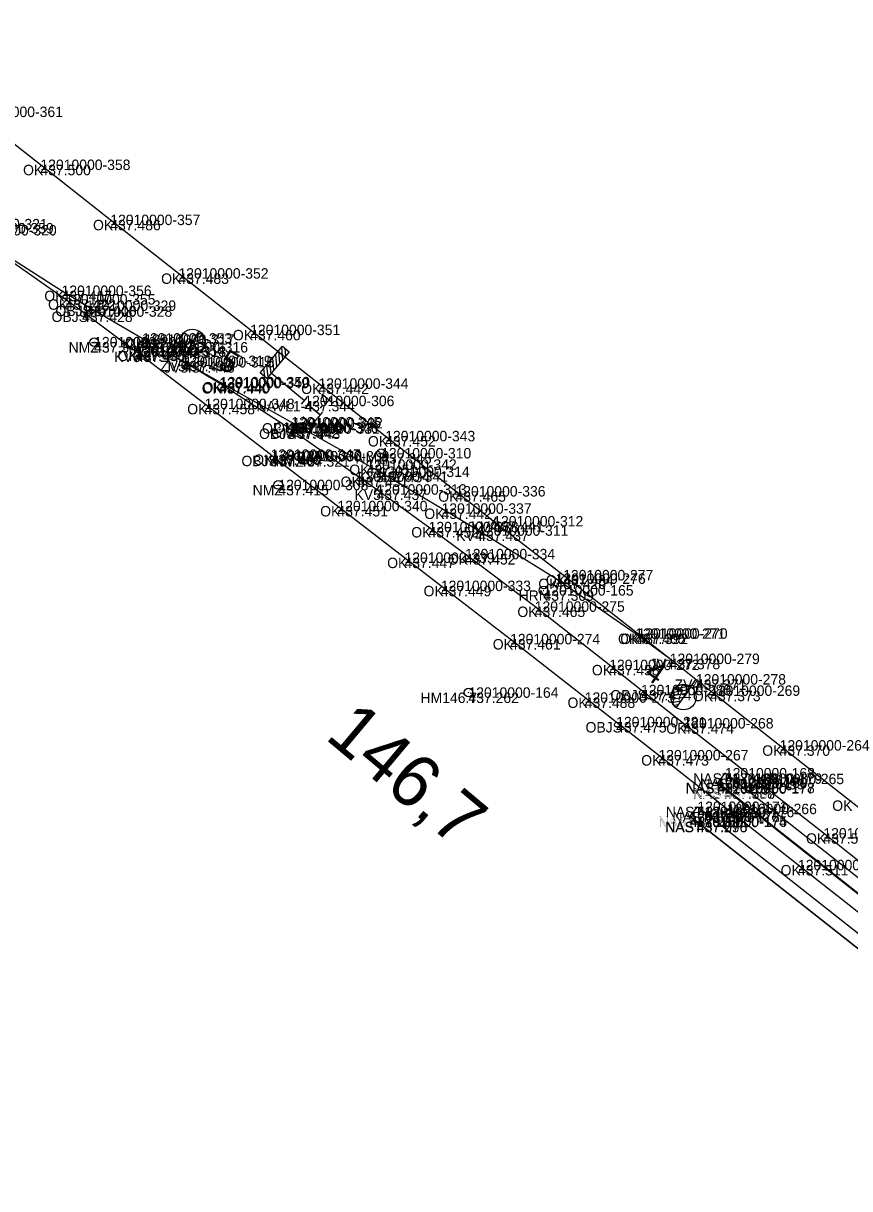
# Model space of a CAD drawing. Extents: x -653665 to -652742, y -1166300 to -1165487.
# Drawn here: x -653400 to -653305, y -1165811.3 to -1165677.3 of the extents above; entities that cross this region are included whole.
import ezdxf

# ---------------------------------------------------------------- set-up
doc = ezdxf.new("R2010")
doc.units = 0
for name, color, linetype in [('Vrstva 1', 7, 'Continuous'), ('Vrstva 14', 7, 'Continuous'), ('Vrstva 2', 7, 'Continuous'), ('Vrstva 50', 7, 'Continuous'), ('Vrstva 6', 7, 'Continuous'), ('Vrstva 60', 7, 'Continuous'), ('Vrstva 61', 7, 'Continuous'), ('Vrstva 62', 7, 'Continuous'), ('Vrstva 7', 7, 'Continuous')]:
    doc.layers.add(name, color=color, linetype=linetype)

msp = doc.modelspace()

# ---------------------------------------------------------------- linework, layer by layer
at = {"layer": 'Vrstva 1'}
for points in [[(-653322.72, -1165752.72), (-653325.73, -1165750.35), (-653329.43, -1165747.45), (-653337.98, -1165740.73), (-653346.02, -1165734.53), (-653350.36, -1165731.09), (-653358.44, -1165724.74), (-653366.11, -1165718.7), (-653373.96, -1165712.53), (-653382.2, -1165706.04), (-653390.04, -1165699.88), (-653398.07, -1165693.55), (-653405.83, -1165687.47), (-653413.9, -1165681.16), (-653418.86, -1165677.28)], [(-653303.11, -1165780.26), (-653310.99, -1165774.05), (-653319.17, -1165767.61), (-653327.03, -1165761.43), (-653331.89, -1165757.62), (-653335.5, -1165754.8), (-653344.08, -1165748.08), (-653352.04, -1165741.96), (-653356.22, -1165738.72), (-653363.93, -1165732.78), (-653371.45, -1165727), (-653371.62, -1165726.86), (-653379.2, -1165721.04), (-653387.07, -1165715.03), (-653387.21, -1165714.92), (-653393.27, -1165710.42), (-653395.2, -1165709.02), (-653406.55, -1165701.06), (-653406.89, -1165700.83), (-653407.58, -1165700.37)], [(-653381.84, -1165716.08), (-653384.56, -1165714.53), (-653386.13, -1165713.64), (-653386.38, -1165713.51), (-653392.82, -1165709.75), (-653395.64, -1165708.03), (-653406.55, -1165701.06), (-653406.89, -1165700.83), (-653407.58, -1165700.37)], [(-653322.72, -1165752.72), (-653325.73, -1165750.35), (-653329.7, -1165747.45), (-653338.85, -1165741.13), (-653347.74, -1165735.6), (-653351.96, -1165733.07), (-653359.08, -1165728.84), (-653360.57, -1165728.02), (-653369.24, -1165723.15), (-653377.44, -1165718.54), (-653381.54, -1165716.25), (-653381.84, -1165716.08)], [(-653300.38, -1165776.48), (-653308.07, -1165770.41), (-653316.04, -1165764.16), (-653324.15, -1165757.77), (-653329.03, -1165753.94), (-653332.69, -1165751.05), (-653341.25, -1165744.34), (-653349.26, -1165738.31), (-653353.45, -1165735.2), (-653359.43, -1165730.88), (-653361.58, -1165729.39), (-653369.56, -1165723.78), (-653377.53, -1165718.65), (-653381.54, -1165716.25), (-653381.84, -1165716.08)], [(-653297.59, -1165772.52), (-653305.06, -1165766.63), (-653313.1, -1165760.3), (-653321.09, -1165754.02), (-653322.72, -1165752.72)]]:
    msp.add_lwpolyline(points, dxfattribs=at)
at = {"layer": 'Vrstva 14'}
for points in [[(-653264.73, -1165806.58), (-653318.56, -1165764.12), (-653319.39, -1165763.51), (-653320.24, -1165764.59), (-653320.26, -1165764.64), (-653319.44, -1165765.26), (-653265.62, -1165807.73), (-653264.04, -1165808.96), (-653264.01, -1165808.93), (-653258.45, -1165813.32), (-653255.28, -1165815.81), (-653252.89, -1165817.67), (-653252.91, -1165817.71), (-653185.94, -1165870.54), (-653160.89, -1165890.22), (-653160.13, -1165890.87), (-653160.09, -1165890.83), (-653159.23, -1165889.74), (-653160.03, -1165889.1), (-653185.12, -1165869.34), (-653252.03, -1165816.59), (-653254.4, -1165814.7), (-653257.6, -1165812.25), (-653263.18, -1165807.82)], [(-653323.43, -1165768.49), (-653323.42, -1165768.47), (-653322.55, -1165767.36), (-653321.77, -1165767.96), (-653260.92, -1165815.93), (-653260.66, -1165816.11), (-653257.48, -1165818.59), (-653188.19, -1165873.27), (-653163.42, -1165892.82), (-653162.59, -1165893.47), (-653163.54, -1165894.55), (-653163.55, -1165894.57), (-653164.32, -1165893.92), (-653188.97, -1165874.49), (-653261.81, -1165817.03), (-653322.62, -1165769.1)]]:
    msp.add_lwpolyline(points, close=True, dxfattribs=at)
for points in [[(-653320.24, -1165764.59), (-653319.41, -1165765.19), (-653265.58, -1165807.68), (-653264.01, -1165808.93)], [(-653323.42, -1165768.47), (-653322.59, -1165769.06), (-653261.78, -1165817.01), (-653188.99, -1165874.41), (-653164.29, -1165893.89), (-653163.54, -1165894.55)]]:
    msp.add_lwpolyline(points, dxfattribs=at)
at = {"layer": 'Vrstva 2'}
for p, q in [((-653385.88, -1165713.21), (-653386.38, -1165714.08)), ((-653381.33, -1165715.19), (-653379.87, -1165712.66)), ((-653380.59, -1165713.91), (-653379.19, -1165713.53)), ((-653380.32, -1165713.45), (-653379.34, -1165713.18)), ((-653380.06, -1165712.99), (-653379.6, -1165712.86)), ((-653386.78, -1165714.62), (-653387.36, -1165715.44)), ((-653381.23, -1165715.24), (-653379.4, -1165714.75)), ((-653381.12, -1165714.82), (-653379.19, -1165714.31)), ((-653380.86, -1165714.37), (-653379.14, -1165713.91)), ((-653381.33, -1165715.19), (-653381.84, -1165716.08)), ((-653381.33, -1165715.19), (-653381.33, -1165715.19)), ((-653358.83, -1165728.4), (-653359.33, -1165729.27)), ((-653359.14, -1165730.47), (-653359.72, -1165731.29)), ((-653347.49, -1165735.16), (-653347.99, -1165736.03)), ((-653345.73, -1165734.12), (-653346.3, -1165734.94)), ((-653323.55, -1165753.91), (-653325.52, -1165754.25)), ((-653323.4, -1165753.5), (-653325.27, -1165753.83)), ((-653323.31, -1165753.56), (-653324.99, -1165755.96)), ((-653323.31, -1165753.56), (-653322.72, -1165752.72)), ((-653323.31, -1165753.56), (-653323.31, -1165753.56)), ((-653323.85, -1165754.34), (-653325.6, -1165754.65)), ((-653324.16, -1165754.78), (-653325.58, -1165755.03)), ((-653324.46, -1165755.21), (-653325.46, -1165755.39)), ((-653324.77, -1165755.65), (-653325.24, -1165755.73))]:
    msp.add_line(p, q, dxfattribs=at)
for centre in [(-653380.6, -1165713.92), (-653324.15, -1165754.76)]:
    msp.add_circle(centre, 1.46, dxfattribs=at)
for centre, start, end in [((-653380.6, -1165713.93), 240.0196, 59.9804), ((-653324.15, -1165754.76), 55.0196, 234.9804)]:
    msp.add_arc(centre, 1.46, start, end, dxfattribs=at)
at = {"layer": 'Vrstva 50'}
for p, q in [((-653391.94, -1165713.94), (-653391.84, -1165713.94)), ((-653368.36, -1165727.06), (-653368.26, -1165727.06)), ((-653358.95, -1165726.71), (-653358.85, -1165726.71)), ((-653370.77, -1165730.36), (-653370.67, -1165730.36)), ((-653340.29, -1165742.48), (-653340.19, -1165742.48))]:
    msp.add_line(p, q, dxfattribs=at)
for centre in [(-653391.89, -1165713.94), (-653368.31, -1165727.06), (-653358.9, -1165726.71), (-653370.72, -1165730.36), (-653340.24, -1165742.48)]:
    msp.add_circle(centre, 0.5, dxfattribs=at)
at = {"layer": 'Vrstva 6'}
for p, q in [((-653370.7, -1165714.95), (-653370.58, -1165716.35)), ((-653370.36, -1165714.54), (-653370.24, -1165715.95)), ((-653369.97, -1165714.64), (-653369.9, -1165715.54)), ((-653371.72, -1165716.16), (-653371.6, -1165717.57)), ((-653371.38, -1165715.76), (-653371.26, -1165717.17)), ((-653371.04, -1165715.35), (-653370.92, -1165716.76)), ((-653372.41, -1165716.98), (-653372.32, -1165717.89)), ((-653372.07, -1165716.57), (-653371.94, -1165717.98)), ((-653367.73, -1165720.7), (-653371.54, -1165717.5)), ((-653368.05, -1165721.08), (-653367.4, -1165720.32))]:
    msp.add_line(p, q, dxfattribs=at)
msp.add_lwpolyline([(-653372.06, -1165718.11), (-653372.82, -1165717.47), (-653370.25, -1165714.41), (-653369.48, -1165715.05)], close=True, dxfattribs=at)
at = {"layer": 'Vrstva 60'}
for p, q in [((-653398.07, -1165693.55), (-653398.07, -1165693.55)), ((-653390.04, -1165699.88), (-653390.04, -1165699.88)), ((-653382.2, -1165706.04), (-653382.2, -1165706.04)), ((-653395.64, -1165708.03), (-653395.64, -1165708.03)), ((-653395.2, -1165709.02), (-653395.2, -1165709.02)), ((-653392.82, -1165709.75), (-653392.82, -1165709.75)), ((-653393.27, -1165710.42), (-653393.27, -1165710.42)), ((-653386.38, -1165713.51), (-653386.38, -1165713.51)), ((-653386.13, -1165713.64), (-653386.13, -1165713.64)), ((-653373.96, -1165712.53), (-653373.96, -1165712.53)), ((-653391.89, -1165713.94), (-653391.89, -1165713.94)), ((-653387.21, -1165714.92), (-653387.21, -1165714.92)), ((-653387.07, -1165715.03), (-653387.07, -1165715.03)), ((-653384.56, -1165714.53), (-653384.56, -1165714.53)), ((-653381.84, -1165716.08), (-653381.84, -1165716.08)), ((-653381.54, -1165716.25), (-653381.54, -1165716.25)), ((-653377.53, -1165718.65), (-653377.53, -1165718.65)), ((-653377.44, -1165718.54), (-653377.44, -1165718.54)), ((-653366.11, -1165718.7), (-653366.11, -1165718.7)), ((-653379.2, -1165721.04), (-653379.2, -1165721.04)), ((-653367.73, -1165720.7), (-653367.73, -1165720.7)), ((-653369.24, -1165723.15), (-653369.24, -1165723.15)), ((-653369.56, -1165723.78), (-653369.56, -1165723.78)), ((-653369.41, -1165723.87), (-653369.41, -1165723.87)), ((-653369.07, -1165723.25), (-653369.07, -1165723.25)), ((-653358.44, -1165724.74), (-653358.44, -1165724.74)), ((-653371.62, -1165726.86), (-653371.62, -1165726.86)), ((-653371.45, -1165727), (-653371.45, -1165727)), ((-653368.31, -1165727.06), (-653368.31, -1165727.06)), ((-653358.9, -1165726.71), (-653358.9, -1165726.71)), ((-653360.57, -1165728.02), (-653360.57, -1165728.02)), ((-653361.58, -1165729.39), (-653361.58, -1165729.39)), ((-653359.08, -1165728.84), (-653359.08, -1165728.84)), ((-653370.72, -1165730.36), (-653370.72, -1165730.36)), ((-653359.43, -1165730.88), (-653359.43, -1165730.88)), ((-653350.36, -1165731.09), (-653350.36, -1165731.09)), ((-653363.93, -1165732.78), (-653363.93, -1165732.78)), ((-653351.96, -1165733.07), (-653351.96, -1165733.07)), ((-653353.45, -1165735.2), (-653353.45, -1165735.2)), ((-653346.02, -1165734.53), (-653346.02, -1165734.53)), ((-653347.74, -1165735.6), (-653347.74, -1165735.6)), ((-653356.22, -1165738.72), (-653356.22, -1165738.72)), ((-653349.26, -1165738.31), (-653349.26, -1165738.31)), ((-653338.85, -1165741.13), (-653338.85, -1165741.13)), ((-653337.98, -1165740.73), (-653337.98, -1165740.73)), ((-653352.04, -1165741.96), (-653352.04, -1165741.96)), ((-653340.24, -1165742.48), (-653340.24, -1165742.48)), ((-653341.25, -1165744.34), (-653341.25, -1165744.34)), ((-653344.08, -1165748.08), (-653344.08, -1165748.08)), ((-653329.7, -1165747.45), (-653329.7, -1165747.45)), ((-653329.43, -1165747.45), (-653329.43, -1165747.45)), ((-653332.69, -1165751.05), (-653332.69, -1165751.05)), ((-653325.73, -1165750.35), (-653325.73, -1165750.35)), ((-653329.03, -1165753.94), (-653329.03, -1165753.94)), ((-653322.72, -1165752.72), (-653322.72, -1165752.72)), ((-653348.87, -1165754.23), (-653348.87, -1165754.23)), ((-653335.5, -1165754.8), (-653335.5, -1165754.8)), ((-653321.09, -1165754.02), (-653321.09, -1165754.02)), ((-653331.89, -1165757.62), (-653331.89, -1165757.62)), ((-653324.15, -1165757.77), (-653324.15, -1165757.77)), ((-653313.1, -1165760.3), (-653313.1, -1165760.3)), ((-653327.03, -1165761.43), (-653327.03, -1165761.43)), ((-653320.26, -1165764.64), (-653320.26, -1165764.64)), ((-653320.24, -1165764.59), (-653320.24, -1165764.59)), ((-653319.39, -1165763.51), (-653319.39, -1165763.51)), ((-653318.56, -1165764.12), (-653318.56, -1165764.12)), ((-653316.04, -1165764.16), (-653316.04, -1165764.16)), ((-653319.44, -1165765.26), (-653319.44, -1165765.26)), ((-653319.41, -1165765.19), (-653319.41, -1165765.19)), ((-653322.55, -1165767.36), (-653322.55, -1165767.36)), ((-653305.06, -1165766.63), (-653305.06, -1165766.63)), ((-653323.43, -1165768.49), (-653323.43, -1165768.49)), ((-653323.42, -1165768.47), (-653323.42, -1165768.47)), ((-653321.77, -1165767.96), (-653321.77, -1165767.96)), ((-653319.17, -1165767.61), (-653319.17, -1165767.61)), ((-653322.62, -1165769.1), (-653322.62, -1165769.1)), ((-653322.59, -1165769.06), (-653322.59, -1165769.06)), ((-653308.07, -1165770.41), (-653308.07, -1165770.41)), ((-653310.99, -1165774.05), (-653310.99, -1165774.05))]:
    msp.add_line(p, q, dxfattribs=at)
at = {"layer": 'Vrstva 7'}
msp.add_line((-653348.91, -1165754.2), (-653348.83, -1165754.27), dxfattribs=at)
msp.add_circle((-653348.87, -1165754.23), 0.5, dxfattribs=at)

# ---------------------------------------------------------------- texts
at = {"layer": 'Vrstva 2'}
for s, rotation, p in [('5', 330, (-653377.78, -1165716.8)), ('4', 325, (-653328.83, -1165752.37))]:
    msp.add_text(s, height=2.5, rotation=rotation, dxfattribs=at).set_placement(p)
at = {"layer": 'Vrstva 6'}
msp.add_text('L1-4', height=1.5, rotation=50, dxfattribs=at).set_placement((-653366.94, -1165723.67))
at = {"layer": 'Vrstva 60'}
for s, p in [('12010000-361', (-653405.83, -1165688.06)), ('12010000-358', (-653398.07, -1165694.15)), ('12010000-321', (-653407.58, -1165700.97)), ('12010000-359', (-653406.89, -1165701.44)), ('12010000-357', (-653390.04, -1165700.48)), ('12010000-320', (-653406.55, -1165701.67)), ('12010000-352', (-653382.2, -1165706.64)), ('12010000-356', (-653395.64, -1165708.63)), ('12010000-355', (-653395.2, -1165709.62)), ('12010000-329', (-653392.82, -1165710.35)), ('12010000-328', (-653393.27, -1165711.02)), ('12010000-351', (-653373.96, -1165713.13)), ('12010000-303', (-653391.89, -1165714.54)), ('12010000-353', (-653386.38, -1165714.11)), ('12010000-317', (-653386.13, -1165714.24)), ('12010000-354', (-653387.21, -1165715.52)), ('12010000-318', (-653387.07, -1165715.63)), ('12010000-316', (-653384.56, -1165715.13)), ('12010000-319', (-653381.84, -1165716.69)), ('12010000-315', (-653381.54, -1165716.85)), ('12010000-349', (-653377.53, -1165719.25)), ('12010000-350', (-653377.44, -1165719.14)), ('12010000-344', (-653366.11, -1165719.3)), ('12010000-348', (-653379.2, -1165721.64)), ('12010000-306', (-653367.73, -1165721.3)), ('12010000-346', (-653369.56, -1165724.38)), ('12010000-345', (-653369.24, -1165723.75)), ('12010000-332', (-653369.07, -1165723.85)), ('12010000-331', (-653369.41, -1165724.47)), ('12010000-343', (-653358.44, -1165725.34)), ('12010000-347', (-653371.62, -1165727.47)), ('12010000-330', (-653371.45, -1165727.6)), ('12010000-309', (-653368.31, -1165727.66)), ('12010000-310', (-653358.9, -1165727.31)), ('12010000-342', (-653360.57, -1165728.62)), ('12010000-314', (-653359.08, -1165729.44)), ('12010000-308', (-653370.72, -1165730.96)), ('12010000-341', (-653361.58, -1165729.99)), ('12010000-313', (-653359.43, -1165731.48)), ('12010000-336', (-653350.36, -1165731.69)), ('12010000-340', (-653363.93, -1165733.38)), ('12010000-337', (-653351.96, -1165733.67)), ('12010000-338', (-653353.45, -1165735.8)), ('12010000-311', (-653347.74, -1165736.2)), ('12010000-312', (-653346.02, -1165735.13)), ('12010000-334', (-653349.26, -1165738.91)), ('12010000-339', (-653356.22, -1165739.32)), ('12010000-276', (-653338.85, -1165741.73)), ('12010000-277', (-653337.98, -1165741.33)), ('12010000-333', (-653352.04, -1165742.56)), ('12010000-165', (-653340.24, -1165743.08)), ('12010000-275', (-653341.25, -1165744.94)), ('12010000-271', (-653329.7, -1165748.05)), ('12010000-270', (-653329.43, -1165748.04)), ('12010000-274', (-653344.08, -1165748.68)), ('12010000-279', (-653325.73, -1165750.95)), ('12010000-272', (-653332.69, -1165751.65)), ('12010000-278', (-653322.72, -1165753.31)), ('12010000-164', (-653348.87, -1165754.83)), ('12010000-280', (-653329.03, -1165754.54)), ('12010000-269', (-653321.09, -1165754.61)), ('12010000-273', (-653335.5, -1165755.4)), ('12010000-281', (-653331.89, -1165758.22)), ('12010000-268', (-653324.15, -1165758.36)), ('12010000-264', (-653313.1, -1165760.9)), ('12010000-267', (-653327.03, -1165762.03)), ('12010000-168', (-653319.39, -1165764.1)), ('12010000-170', (-653320.26, -1165765.24)), ('12010000-169', (-653320.24, -1165765.19)), ('12010000-177', (-653319.44, -1165765.86)), ('12010000-178', (-653319.41, -1165765.79)), ('12010000-179', (-653318.56, -1165764.72)), ('12010000-265', (-653316.04, -1165764.76)), ('12010000-171', (-653322.55, -1165767.96)), ('12010000-176', (-653321.77, -1165768.56)), ('12010000-266', (-653319.17, -1165768.21)), ('12010000-173', (-653323.43, -1165769.09)), ('12010000-172', (-653323.42, -1165769.07)), ('12010000-174', (-653322.62, -1165769.7)), ('12010000-175', (-653322.59, -1165769.66)), ('12010000-262', (-653308.07, -1165771.01)), ('12010000-261', (-653310.99, -1165774.66))]:
    msp.add_text(s, height=1.2, dxfattribs=at).set_placement(p)
at = {"layer": 'Vrstva 61'}
for s, p in [('437.500', (-653398.07, -1165694.75)), ('437.486', (-653390.04, -1165701.08)), ('437.483', (-653382.2, -1165707.24)), ('437.417', (-653395.64, -1165709.23)), ('437.422', (-653395.2, -1165710.22)), ('437.418', (-653392.82, -1165710.95)), ('437.428', (-653393.27, -1165711.62)), ('437.446', (-653386.38, -1165714.71)), ('437.441', (-653386.13, -1165714.84)), ('437.460', (-653373.96, -1165713.73)), ('437.343', (-653391.89, -1165715.14)), ('437.436', (-653387.21, -1165716.12)), ('437.441', (-653387.07, -1165716.23)), ('437.445', (-653384.56, -1165715.73)), ('437.438', (-653381.84, -1165717.28)), ('437.446', (-653381.54, -1165717.45)), ('437.440', (-653377.53, -1165719.85)), ('437.440', (-653377.44, -1165719.74)), ('437.442', (-653366.11, -1165719.9)), ('437.458', (-653379.2, -1165722.24)), ('437.344', (-653367.73, -1165721.9)), ('437.445', (-653369.24, -1165724.35)), ('437.442', (-653369.56, -1165724.98)), ('437.443', (-653369.41, -1165725.07)), ('437.452', (-653369.07, -1165724.45)), ('437.452', (-653358.44, -1165725.94)), ('437.460', (-653371.62, -1165728.06)), ('437.464', (-653371.45, -1165728.2)), ('437.321', (-653368.31, -1165728.26)), ('437.345', (-653358.9, -1165727.91)), ('437.451', (-653360.57, -1165729.22)), ('437.451', (-653361.58, -1165730.59)), ('437.434', (-653359.08, -1165730.04)), ('437.415', (-653370.72, -1165731.56)), ('437.437', (-653359.43, -1165732.08)), ('437.465', (-653350.36, -1165732.29)), ('437.451', (-653363.93, -1165733.98)), ('437.442', (-653351.96, -1165734.27)), ('437.452', (-653353.45, -1165736.4)), ('437.441', (-653346.02, -1165735.73)), ('437.437', (-653347.74, -1165736.8)), ('437.447', (-653356.22, -1165739.92)), ('437.452', (-653349.26, -1165739.51)), ('437.420', (-653338.85, -1165742.33)), ('437.434', (-653337.98, -1165741.93)), ('437.449', (-653352.04, -1165743.16)), ('437.309', (-653340.24, -1165743.68)), ('437.465', (-653341.25, -1165745.54)), ('437.461', (-653344.08, -1165749.28)), ('437.405', (-653329.7, -1165748.65)), ('437.392', (-653329.43, -1165748.65)), ('437.458', (-653332.69, -1165752.25)), ('437.378', (-653325.73, -1165751.55)), ('437.474', (-653329.03, -1165755.14)), ('437.371', (-653322.72, -1165753.92)), ('437.262', (-653348.87, -1165755.43)), ('437.488', (-653335.5, -1165756)), ('437.373', (-653321.09, -1165755.22)), ('437.475', (-653331.89, -1165758.82)), ('437.474', (-653324.15, -1165758.97)), ('437.370', (-653313.1, -1165761.5)), ('437.473', (-653327.03, -1165762.62)), ('437.415', (-653320.26, -1165765.84)), ('437.518', (-653320.24, -1165765.79)), ('437.443', (-653319.39, -1165764.71)), ('437.586', (-653318.56, -1165765.32)), ('437.499', (-653316.04, -1165765.36)), ('437.338', (-653319.44, -1165766.46)), ('437.707', (-653319.41, -1165766.39)), ('437.481', (-653322.55, -1165768.56)), ('437.251', (-653323.43, -1165769.69)), ('437.519', (-653323.42, -1165769.67)), ('437.556', (-653321.77, -1165769.16)), ('437.487', (-653319.17, -1165768.81)), ('437.296', (-653322.62, -1165770.3)), ('437.678', (-653322.59, -1165770.26)), ('437.510', (-653308.07, -1165771.61)), ('437.511', (-653310.99, -1165775.26))]:
    msp.add_text(s, height=1.2, dxfattribs=at).set_placement(p)
at = {"layer": 'Vrstva 62'}
for s, p in [('OK', (-653400.06, -1165694.75)), ('OK', (-653392.02, -1165701.08)), ('OK', (-653384.19, -1165707.24)), ('OK', (-653397.62, -1165709.23)), ('OK', (-653397.19, -1165710.22)), ('OBJS', (-653396.34, -1165710.95)), ('OBJS', (-653396.79, -1165711.62)), ('KV6', (-653388.66, -1165714.84)), ('OK', (-653388.36, -1165714.71)), ('OK', (-653375.94, -1165713.73)), ('NMZ', (-653394.83, -1165715.14)), ('KV6', (-653389.6, -1165716.23)), ('OK', (-653389.2, -1165716.12)), ('OK', (-653386.55, -1165715.73)), ('ZV5', (-653384.31, -1165717.28)), ('JV5', (-653383.85, -1165717.45)), ('OK', (-653379.52, -1165719.85)), ('OK', (-653379.43, -1165719.74)), ('OK', (-653368.09, -1165719.9)), ('OK', (-653381.19, -1165722.24)), ('NAVL1-4', (-653373.23, -1165721.9)), ('OK', (-653371.22, -1165724.35)), ('OBJS', (-653372.93, -1165725.07)), ('OBJS', (-653372.59, -1165724.45)), ('OK', (-653371.54, -1165724.98)), ('OK', (-653360.42, -1165725.94)), ('OBJS', (-653374.96, -1165728.2)), ('OK', (-653373.6, -1165728.06)), ('NMZ', (-653371.26, -1165728.26)), ('NMZ', (-653361.85, -1165727.91)), ('OK', (-653362.56, -1165729.22)), ('OK', (-653363.56, -1165730.59)), ('KV5', (-653361.62, -1165730.04)), ('NMZ', (-653373.67, -1165731.56)), ('KV5', (-653361.97, -1165732.08)), ('OK', (-653352.34, -1165732.29)), ('OK', (-653365.91, -1165733.98)), ('OK', (-653353.94, -1165734.27)), ('OK', (-653355.44, -1165736.4)), ('KV4', (-653348.55, -1165735.73)), ('KV4', (-653350.27, -1165736.8)), ('OK', (-653358.21, -1165739.92)), ('OK', (-653351.24, -1165739.51)), ('OK', (-653340.83, -1165742.33)), ('OK', (-653339.97, -1165741.93)), ('OK', (-653354.03, -1165743.16)), ('HRN', (-653343.1, -1165743.68)), ('OK', (-653343.24, -1165745.54)), ('OK', (-653346.07, -1165749.28)), ('OK', (-653331.68, -1165748.65)), ('OK', (-653331.42, -1165748.65)), ('OK', (-653334.68, -1165752.25)), ('JV4', (-653328.03, -1165751.55)), ('OBJS', (-653332.55, -1165755.14)), ('ZV4', (-653325.17, -1165753.92)), ('HM146.7', (-653354.38, -1165755.43)), ('OK', (-653337.48, -1165756)), ('OK', (-653323.07, -1165755.22)), ('OBJS', (-653335.41, -1165758.82)), ('OK', (-653326.13, -1165758.97)), ('OK', (-653315.09, -1165761.5)), ('OK', (-653329.01, -1165762.62)), ('NAST', (-653323.9, -1165765.84)), ('NAST', (-653323.88, -1165765.79)), ('NAST', (-653323.03, -1165764.71)), ('NAST', (-653322.2, -1165765.32)), ('OK', (-653318.02, -1165765.36)), ('NAST', (-653323.08, -1165766.46)), ('NAST', (-653323.05, -1165766.39)), ('NAST', (-653326.19, -1165768.56)), ('OK', (-653307.05, -1165767.83)), ('NAST', (-653327.07, -1165769.69)), ('NAST', (-653327.05, -1165769.67)), ('NAST', (-653325.41, -1165769.16)), ('OK', (-653321.16, -1165768.81)), ('NAST', (-653326.26, -1165770.3)), ('NAST', (-653326.23, -1165770.26)), ('OK', (-653310.06, -1165771.61)), ('OK', (-653312.98, -1165775.26))]:
    msp.add_text(s, height=1.2, dxfattribs=at).set_placement(p)
at = {"layer": 'Vrstva 7'}
msp.add_text('146,7', height=6, rotation=320, dxfattribs=at).set_placement((-653365.48, -1165759.46))

doc.saveas('drawing.dxf')
